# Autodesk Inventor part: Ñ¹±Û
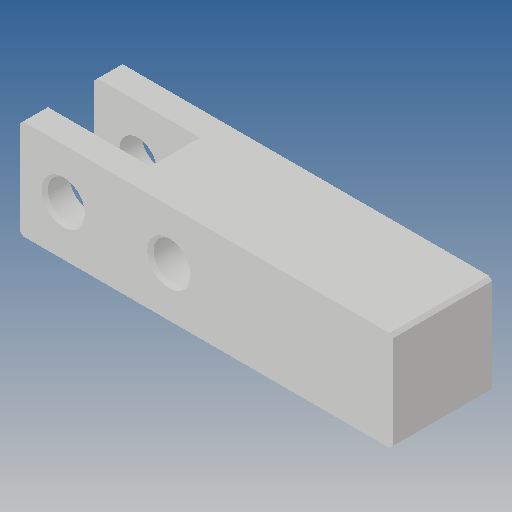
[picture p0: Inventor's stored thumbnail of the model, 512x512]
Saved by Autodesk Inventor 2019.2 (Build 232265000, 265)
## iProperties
Created: 2013-07
Part Number: Ñ¹±Û
Material: Ogólny
Document SubType Name: Modeling
Designer: CADENGINEERING4
Density: 1 g/cm^3
Appearance: Domyślna
Author: CADENGINEERING4
Revision Number: ÈÎºÎ
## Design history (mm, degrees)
feature "µ¹½Ç1"
node "Bryła1"
